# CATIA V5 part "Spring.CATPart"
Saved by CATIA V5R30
Part number: Part1
Bounding box of the stored display mesh (mm): x -50 to 50, y -44.999 to 44.983, z -4.984 to 154.984
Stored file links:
  D:\PROJECTS\CATIA V56R 2020\Resources\Parts File\c19_catia_v5_6r2020_inp\c19_catia_v5_6r2020_inp\c19_catia_v5_6r2020_inp\C19_tut_01.CATPart\Spring.CATPart
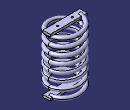
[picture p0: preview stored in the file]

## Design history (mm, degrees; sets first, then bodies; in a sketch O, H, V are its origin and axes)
Body1 (main body)
  Point1: (0, 0, 0)
  Point2: (0, 0, 150)
  Line1: type PtPt, FirstPoint Point2, SecondPoint Point1
  Point3: (40, 0, 0)
  Helix1: Direction Line1, RefPoint Point3, Pitch 20, Height 150, TaperAngle 0, Revolutions 1
  Plane1: type Normal, Curve Helix1, RefPoint vertex of Helix1, Ratio 0
  Sketch1 on Plane1, origin (0, -11.8615, 0.9439), H (1, 0, 0), V (0, 0.0793, 0.9968)
    circle A1 centre (-40, 149.5273) radius 5
    point P1 (-40, 149.5273)
    reference projected point E1 (-40, 149.5273) from vertex of Helix1
    radius A1 = 5
    coincidence: P1 E1
  Rib1: profile Sketch1, centre curve Helix1
  Sketch2 on xy-plane, origin (0, 0, 0), H (1, 0, 0), V (0, 1, 0)
    line L1 (-50, 10) -> (50, 10)
    line L2 (50, 10) -> (50, -10)
    line L3 (50, -10) -> (-50, -10)
    line L4 (-50, -10) -> (-50, 10)
    length L1 = 100
    distance L1 L3 = 20
    horizontal: L1 H, L3 H
    vertical: L2 V, L4 V
    symmetry: L3 L1 H, L2 L4 V
  Pad1: profile Sketch2, direction (0, 0, 1), length 3, mirrored extent
  Sketch3 on start face of Pad1, origin (0, 0, -3), H (1, 0, 0), V (0, -1, 0)
    circle A1 centre (-24.223, 0) radius 2.5
    point P1 (-24.223, 0)
    circle A2 centre (24.223, 0) radius 2.5
    point P2 (24.223, 0)
    radius A2 = 2.5
    coincidence: P1 H, P2 H
    symmetry: A2 A1 V
  Pocket1: profile Sketch3, direction (0, 0, 1), length 3
  Plane2: type Offset, RefPlane xy-plane, Offset 150
  Sketch4 on Plane2, origin (0, 0, 150), H (1, 0, 0), V (0, 1, 0)
    line L1 (-50, 10) -> (50, 10)
    line L2 (50, 10) -> (50, -10)
    line L3 (50, -10) -> (-50, -10)
    line L4 (-50, -10) -> (-50, 10)
    reference projected line E1 (50, -10) -> (50, 10) from edge [face of Pad1 from Sketch2.L2 | end face of Pad1]
    reference projected line E2 (-50, 10) -> (-50, -10) from edge [face of Pad1 from Sketch2.L4 | end face of Pad1]
    reference projected line E3 (-50, -10) -> (50, -10) from edge [face of Pad1 from Sketch2.L3 | end face of Pad1]
    reference projected line E4 (50, 10) -> (-50, 10) from edge [face of Pad1 from Sketch2.L1 | end face of Pad1]
    horizontal: L1 H, L3 H
    vertical: L2 V, L4 V
    coincidence: L2 E1, L4 E2, E3 L3, L1 E4
  Pad2: profile Sketch4, direction (0, 0, 1), length 3, mirrored extent
  Sketch5 on end face of Pad2, origin (0, 0, 153), H (1, 0, 0), V (0, 1, 0)
    circle A1 centre (-20.0406, 0) radius 2.5674
    point P1 (-20.0406, 0)
    circle A2 centre (20.0406, 0) radius 2.5674
    coincidence: P1 H
    symmetry: A1 A2 V
  Pocket2: profile Sketch5, direction (0, 0, -1), through (limit type 6)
